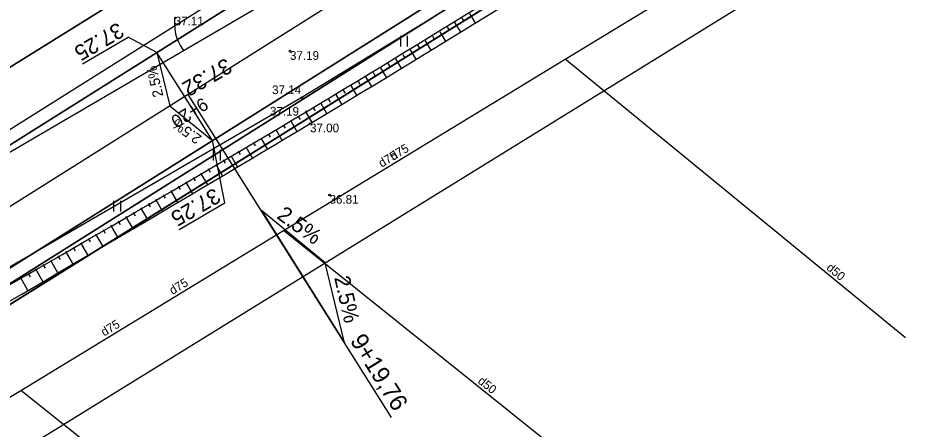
# Model space of a CAD drawing. Extents: x 469981 to 472086, y 246785 to 247785.
# Drawn here: x 471161.2 to 471212.4, y 247215.1 to 247238.7 of the extents above; entities that cross this region are included whole.
import ezdxf

# ---------------------------------------------------------------- set-up
doc = ezdxf.new("R2010")
doc.units = 0
for name, color, linetype in [('0_922', 7, 'Continuous'), ('0_Asfalta_mala', 7, 'Continuous'), ('0_Asfalta_Nomale', 7, 'Continuous'), ('0_Ruut_Braukt', 7, 'Continuous'), ('0_Ruut_nomale', 7, 'Continuous'), ('0_vertikals', 7, 'Continuous'), ('0_vertkals_cipari', 7, 'Continuous'), ('0_Virazjas', 7, 'Continuous'), ('21', 7, 'Continuous'), ('6_piketaza', 7, 'Continuous'), ('CELI_CMAL_####_####_#', 7, 'Continuous'), ('DREN_VADP_####_####_#', 7, 'Continuous'), ('DREN_VADP_####_TKST_#', 7, 'Continuous'), ('DREN_VADP_KLKT_####_#', 7, 'Continuous'), ('DREN_VADP_KLKT_TKST_#', 7, 'Continuous'), ('RAMI_UZMR_####_####_#', 7, 'Continuous'), ('RELJ_AATZ_####_TKST_#', 7, 'Continuous'), ('RELJ_ELEM_####_####_#', 7, 'Continuous'), ('RELJ_NOGA_####_####_#', 7, 'Continuous'), ('RELJ_NOGL_####_####_#', 7, 'Continuous'), ('ROBZ_IERR_####_####_#', 7, 'Continuous'), ('ROBZ_PROJ_####_####_#', 7, 'Continuous'), ('TERT_ELEM_####_####_#', 7, 'Continuous'), ('TERT_KONT_####_####_#', 7, 'Continuous')]:
    doc.layers.add(name, color=color, linetype=linetype)

msp = doc.modelspace()

# ---------------------------------------------------------------- linework, layer by layer
at = {"layer": '0_922'}
msp.add_line((471337.911, 247339.41), (471145.574, 247218.36), dxfattribs=at)
at = {"layer": '0_Asfalta_mala'}
for p, q in [((471336.304, 247341.944), (471143.977, 247220.899)), ((471339.517, 247336.876), (471147.172, 247215.821))]:
    msp.add_line(p, q, dxfattribs=at)
at = {"layer": '0_Asfalta_Nomale'}
for p, q in [((471335.903, 247342.577), (471143.577, 247221.534)), ((471339.918, 247336.243), (471147.572, 247215.187))]:
    msp.add_line(p, q, dxfattribs=at)
at = {"layer": '0_Ruut_Braukt'}
for p, q in [((471336.304, 247341.944), (471143.977, 247220.899)), ((471147.172, 247215.821), (471339.517, 247336.876))]:
    msp.add_line(p, q, dxfattribs=at)
at = {"layer": '0_Ruut_nomale'}
for p, q in [((471208.75, 247262.551), (471143.577, 247221.534)), ((471143.977, 247220.899), (471208.786, 247261.688)), ((471209.079, 247254.783), (471147.172, 247215.821)), ((471147.572, 247215.187), (471209.116, 247253.92))]:
    msp.add_line(p, q, dxfattribs=at)
at = {"layer": '0_vertikals'}
for p, q in [((471164.882, 247236.098), (471167.514, 247237.633)), ((471169.165, 247236.752), (471167.514, 247237.633)), ((471173.075, 247228.098), (471172.361, 247231.674)), ((471170.443, 247226.563), (471173.075, 247228.098))]:
    msp.add_line(p, q, dxfattribs=at)
msp.add_lwpolyline([(471169.165, 247236.752), (471169.917, 247233.681), (471172.361, 247231.674)], close=True, dxfattribs=at)
at = {"layer": '0_Virazjas'}
msp.add_line((471182.683, 247215.721), (471170.964, 247234.34), dxfattribs=at)
msp.add_lwpolyline([(471179.973, 247220.026), (471178.846, 247224.633), (471175.179, 247227.643)], close=True, dxfattribs=at)
at = {"layer": '21'}
msp.add_line((471337.911, 247339.41), (471145.574, 247218.36), dxfattribs=at)
at = {"layer": '6_piketaza'}
msp.add_lwpolyline([(471170.897, 247234.002), (471170.63, 247234.425)], dxfattribs=at)
at = {"layer": 'CELI_CMAL_####_####_#'}
for points in [[(471014.161, 247188.048), (471038.308, 247191.645), (471077.61, 247195.71), (471090.836, 247197.337), (471096.461, 247198.582), (471117.856, 247206.682), (471130.197, 247213.261), (471151.631, 247225.738), (471175.407, 247239.608), (471196.168, 247252.49), (471217.229, 247265.52), (471244.784, 247283.359), (471266.102, 247296.914), (471293.433, 247314.365), (471318.262, 247330.084), (471336.637, 247341.969), (471339.45, 247343.841), (471340.412, 247346.293), (471340.291, 247349.818), (471339.894, 247353.24), (471336.901, 247360.015), (471333.813, 247367.721)], [(471347.348, 247327.622), (471345.475, 247334.467), (471344.349, 247336.664), (471343.67, 247337.19), (471342.054, 247337.492), (471341.155, 247337.494), (471339.762, 247336.569), (471318.941, 247323.623), (471297.221, 247309.64), (471268.834, 247291.51), (471247.888, 247278.119), (471219.179, 247259.989), (471200.048, 247247.93), (471177.515, 247234.149), (471154.773, 247220.961), (471131.272, 247207.521), (471119.66, 247201.466), (471103.03, 247195.231), (471092.329, 247192.658), (471077.436, 247189.782), (471058.729, 247187.944), (471037.006, 247184.759), (471015.923, 247182.598), (470992.26, 247181.035)]]:
    msp.add_lwpolyline(points, dxfattribs=at)
at = {"layer": 'DREN_VADP_####_####_#'}
for points in [[(471212.287, 247220.314), (471192.686, 247236.365)], [(471196.12, 247210.728), (471176.461, 247226.493)], [(471180.883, 247201.694), (471161.317, 247217.281)]]:
    msp.add_lwpolyline(points, dxfattribs=at)
at = {"layer": 'DREN_VADP_KLKT_####_#'}
msp.add_lwpolyline([(471146.746, 247208.584), (471161.317, 247217.281), (471176.461, 247226.493), (471192.686, 247236.365), (471206.685, 247244.884), (471222.566, 247254.545)], dxfattribs=at)
at = {"layer": 'RAMI_UZMR_####_####_#'}
msp.add_lwpolyline([(471380.292, 247353.371), (471352.036, 247335.759), (471352.913, 247327.325), (471347.47, 247325.392), (471345.187, 247325.919), (471342.905, 247329.082), (471319.551, 247313.443), (471222.661, 247251.69), (471157.352, 247211.35), (471144.207, 247202.916), (471131.364, 247196.59), (471113.303, 247188.858), (471105.677, 247188.256), (471083.576, 247183.01), (471075.205, 247182.665), (471043.397, 247175.418), (471016.707, 247172.079), (470997.217, 247171.376)], dxfattribs=at)
at = {"layer": 'RELJ_ELEM_####_####_#'}
for centre in [(471176.829, 247236.826), (471177.515, 247234.149), (471177.77, 247233.339), (471177.985, 247232.653), (471179.106, 247228.541)]:
    msp.add_circle(centre, 0.05, dxfattribs=at)
at = {"layer": 'RELJ_NOGA_####_####_#'}
for p, q in [((471186.735, 247238.736), (471186.842, 247238.562)), ((471187.159, 247238.999), (471187.52, 247238.419)), ((471185.884, 247238.21), (471185.991, 247238.036)), ((471186.309, 247238.473), (471186.668, 247237.894)), ((471185.032, 247237.686), (471185.139, 247237.512)), ((471185.458, 247237.948), (471185.814, 247237.37)), ((471184.18, 247237.163), (471184.285, 247236.99)), ((471184.606, 247237.424), (471184.96, 247236.846)), ((471183.326, 247236.643), (471183.431, 247236.47)), ((471183.753, 247236.903), (471184.106, 247236.325)), ((471182.47, 247236.125), (471182.575, 247235.951)), ((471182.898, 247236.384), (471183.249, 247235.804)), ((471182.042, 247235.867), (471182.393, 247235.286)), ((471181.185, 247235.352), (471181.534, 247234.768)), ((471181.614, 247235.609), (471181.719, 247235.434)), ((471179.896, 247234.585), (471180.001, 247234.408)), ((471180.326, 247234.84), (471180.675, 247234.252)), ((471180.756, 247235.096), (471180.86, 247234.92)), ((471179.034, 247234.077), (471179.139, 247233.898)), ((471179.465, 247234.331), (471179.815, 247233.738)), ((471178.171, 247233.572), (471178.277, 247233.392)), ((471178.603, 247233.824), (471178.953, 247233.226)), ((471177.306, 247233.07), (471177.412, 247232.887)), ((471177.739, 247233.321), (471178.09, 247232.715)), ((471176.441, 247232.568), (471176.548, 247232.384)), ((471176.874, 247232.819), (471177.229, 247232.207)), ((471175.577, 247232.066), (471175.684, 247231.88)), ((471176.009, 247232.317), (471176.367, 247231.7)), ((471174.712, 247231.565), (471174.821, 247231.377)), ((471175.144, 247231.815), (471175.506, 247231.192)), ((471173.847, 247231.063), (471173.957, 247230.873)), ((471174.279, 247231.314), (471174.644, 247230.684)), ((471172.982, 247230.561), (471173.093, 247230.369)), ((471173.414, 247230.812), (471173.783, 247230.177)), ((471172.117, 247230.059), (471172.229, 247229.866)), ((471172.549, 247230.31), (471172.921, 247229.669)), ((471171.252, 247229.557), (471171.365, 247229.362)), ((471171.684, 247229.808), (471172.059, 247229.161)), ((471170.387, 247229.055), (471170.501, 247228.859)), ((471170.819, 247229.306), (471171.198, 247228.654)), ((471169.522, 247228.553), (471169.637, 247228.355)), ((471169.954, 247228.804), (471170.336, 247228.146)), ((471168.657, 247228.052), (471168.773, 247227.851)), ((471169.089, 247228.303), (471169.475, 247227.638)), ((471167.792, 247227.55), (471167.909, 247227.348)), ((471168.224, 247227.801), (471168.613, 247227.131)), ((471166.927, 247227.048), (471167.045, 247226.844)), ((471167.359, 247227.299), (471167.751, 247226.623)), ((471166.062, 247226.546), (471166.181, 247226.341)), ((471166.494, 247226.797), (471166.89, 247226.115)), ((471165.197, 247226.044), (471165.317, 247225.837)), ((471165.629, 247226.295), (471166.028, 247225.608)), ((471164.332, 247225.542), (471164.453, 247225.334)), ((471164.765, 247225.793), (471165.167, 247225.1)), ((471163.467, 247225.041), (471163.589, 247224.83)), ((471163.9, 247225.291), (471164.305, 247224.592)), ((471162.602, 247224.539), (471162.725, 247224.326)), ((471163.035, 247224.79), (471163.444, 247224.085)), ((471161.737, 247224.037), (471161.861, 247223.823)), ((471162.17, 247224.288), (471162.582, 247223.577)), ((471161.305, 247223.786), (471161.72, 247223.069))]:
    msp.add_line(p, q, dxfattribs=at)
msp.add_spline([(471155.25, 247220.273), (471177.77, 247233.339), (471200.51, 247247.391), (471219.6, 247259.351), (471248.359, 247277.5), (471269.232, 247290.973), (471319.351, 247322.992), (471333.341, 247331.731), (471337.475, 247334.177), (471338.538, 247334.697), (471340.216, 247335.099), (471340.901, 247334.839)], degree=3, dxfattribs=at)
at = {"layer": 'RELJ_NOGL_####_####_#'}
msp.add_spline([(471155.819, 247219.592), (471177.985, 247232.653), (471201.025, 247246.801), (471219.926, 247258.493), (471248.971, 247276.784), (471269.467, 247290.521), (471319.665, 247322.242), (471333.631, 247330.726), (471337.921, 247333.442), (471339.285, 247334.228), (471340.237, 247334.435), (471340.94, 247334.352)], degree=3, dxfattribs=at)
at = {"layer": 'ROBZ_IERR_####_####_#'}
for points in [[(471513.259, 247488.166), (471524.883, 247464.852), (471341.261, 247348.2), (471124.72, 247213.54), (471093.674, 247200.298), (471050.609, 247195.379), (471001.509, 247189.266), (470977.922, 247249.601)], [(471168.816, 247177.651), (471133.176, 247205.05), (471346.741, 247338.478), (471363.107, 247281.069)]]:
    msp.add_lwpolyline(points, dxfattribs=at)
at = {"layer": 'ROBZ_PROJ_####_####_#'}
for points in [[(470613.752, 247179.765), (470688.303, 247197.106), (470783.692, 247219.293), (470809.088, 247224.67), (470845.751, 247226.447), (470876.169, 247225.296), (470921.641, 247209.731), (470967.353, 247194.084), (470989.48, 247188.802), (471001.509, 247189.266), (471050.609, 247195.379), (471093.674, 247200.298), (471124.72, 247213.54), (471341.261, 247348.2), (471524.883, 247464.852)], [(471398.351, 247372.094), (471346.741, 247338.478), (471133.176, 247205.05), (471108.425, 247194.786), (471087.339, 247189.709), (471023.306, 247181.157), (470962.604, 247185.245), (470905.63, 247205.857), (470878.75, 247214.454), (470852.344, 247217.039), (470815.743, 247215.147), (470778.583, 247209.26), (470718.669, 247194.633), (470636.973, 247175.147), (470468.364, 247124.23), (470431.624, 247112.202), (470396.219, 247097.502), (470371.503, 247083.47), (470275.956, 246992.729), (470152.342, 246907.761), (470066.737, 246851.23)]]:
    msp.add_lwpolyline(points, dxfattribs=at)
at = {"layer": 'TERT_ELEM_####_####_#'}
for p, q in [((471183.206, 247237.102), (471183.206, 247237.702)), ((471183.606, 247237.102), (471183.606, 247237.702)), ((471172.421, 247230.536), (471172.421, 247231.136)), ((471172.821, 247230.536), (471172.821, 247231.136)), ((471166.692, 247227.596), (471166.692, 247228.196)), ((471167.092, 247227.596), (471167.092, 247228.196))]:
    msp.add_line(p, q, dxfattribs=at)
at = {"layer": 'TERT_KONT_####_####_#'}
msp.add_spline([(471170.189, 247238.813), (471170.275, 247237.692), (471170.722, 247236.824)], degree=3, dxfattribs=at)

# ---------------------------------------------------------------- texts
at = {"layer": '0_vertkals_cipari'}
for s, height, rotation, p in [('37.25', 0.9, 210.2507, (471166.917, 247238.518)), ('37.32', 0.9, 210.2507, (471173.14, 247236.466)), ('2.5%', 0.5993, 103.0344, (471169.541, 247234.249)), ('2.5%', 0.5993, 144.2467, (471171.793, 247231.908)), ('37.25', 0.9, 210.2507, (471172.477, 247228.983))]:
    msp.add_text(s, height=height, rotation=rotation, dxfattribs=at).set_placement(p)
at = {"layer": '0_Virazjas'}
for s, height, rotation, p in [('2.5%', 0.899, 324.2467, (471176.011, 247227.236)), ('2.5%', 0.899, 282.602, (471179.372, 247223.781)), ('9+19,76', 1, 301.8166, (471180.262, 247220.149))]:
    msp.add_text(s, height=height, rotation=rotation, dxfattribs=at).set_placement(p)
at = {"layer": '6_piketaza'}
msp.add_text('9+20', height=0.75, rotation=212.1849, dxfattribs=at).set_placement((471171.809, 247234.192))
at = {"layer": 'DREN_VADP_####_TKST_#'}
for rotation, p in [(320.6848, (471207.685, 247224.276)), (321.2723, (471187.606, 247217.748))]:
    msp.add_text('d50', height=0.5, rotation=rotation, dxfattribs=at).set_placement(p)
at = {"layer": 'DREN_VADP_KLKT_TKST_#'}
for rotation, p in [(31.3182, (471182.117, 247230.11)), (31.3182, (471182.783, 247230.515)), (31.3144, (471170.069, 247222.781)), (31.3144, (471166.131, 247220.385))]:
    msp.add_text('d75', height=0.5, rotation=rotation, dxfattribs=at).set_placement(p)
at = {"layer": 'RELJ_AATZ_####_TKST_#'}
for s, p in [('37.11', (471170.189, 247238.313)), ('37.19', (471176.829, 247236.326)), ('37.14', (471175.8, 247234.352)), ('37.19', (471175.677, 247233.116)), ('37.00', (471177.985, 247232.153)), ('36.81', (471179.106, 247228.041))]:
    msp.add_text(s, height=0.5, dxfattribs=at).set_placement(p)

doc.saveas('drawing.dxf')
